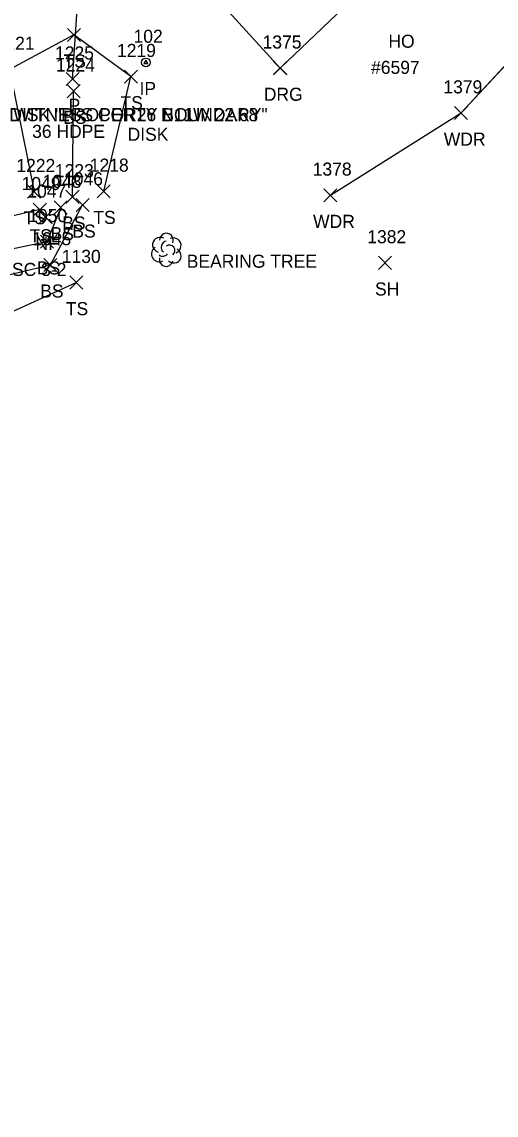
# Model space of a CAD drawing. Extents: x 1528286 to 1556263, y 492387 to 508952.
# Drawn here: x 1528944.2 to 1529016.8, y 492794 to 492961.3 of the extents above; entities that cross this region are included whole.
import ezdxf

# ---------------------------------------------------------------- set-up
doc = ezdxf.new("R2010")
doc.units = 0
for name, color, linetype in [('D_A', 7, 'Continuous'), ('D_C', 7, 'Continuous'), ('D_I', 7, 'Continuous'), ('D_TIC', 7, 'Continuous'), ('DCP', 7, 'Continuous'), ('L_A', 7, 'Continuous'), ('L_C', 7, 'Continuous'), ('L_I', 7, 'Continuous'), ('L_TIC', 7, 'Continuous'), ('LAWA', 7, 'Continuous'), ('LELB', 7, 'Continuous'), ('Level 14', 7, 'Continuous'), ('M_A', 7, 'Continuous'), ('M_C', 7, 'Continuous'), ('M_I', 7, 'Continuous'), ('MPIR', 7, 'Continuous'), ('R_A', 7, 'Continuous'), ('R_I', 7, 'Continuous'), ('R_TIC', 7, 'Continuous'), ('RDG', 7, 'Continuous')]:
    doc.layers.add(name, color=color, linetype=linetype)

msp = doc.modelspace()

# ---------------------------------------------------------------- linework, layer by layer
at = {"layer": 'D_TIC'}
for points in [[(1528950.98, 492951.57), (1528952.98, 492953.57)], [(1528952.98, 492951.57), (1528950.98, 492953.57)], [(1528950.98, 492951.57), (1528952.98, 492953.57)], [(1528952.98, 492951.57), (1528950.98, 492953.57)]]:
    msp.add_lwpolyline(points, dxfattribs=at)
at = {"layer": 'DCP'}
msp.add_lwpolyline([(1528951.98, 492952.57), (1528957.21, 493031.06)], dxfattribs=at)
msp.add_lwpolyline([(1528951.98, 492952.57), (1528957.21, 493031.06)], dxfattribs=at)
at = {"layer": 'L_TIC'}
for points in [[(1528951.19, 492958.33), (1528953.19, 492960.33)], [(1528953.19, 492958.33), (1528951.19, 492960.33)], [(1528951.19, 492958.33), (1528953.19, 492960.33)], [(1528953.19, 492958.33), (1528951.19, 492960.33)], [(1528959.9, 492951.95), (1528961.9, 492953.95)], [(1528961.9, 492951.95), (1528959.9, 492953.95)], [(1528959.9, 492951.95), (1528961.9, 492953.95)], [(1528961.9, 492951.95), (1528959.9, 492953.95)], [(1528951.13, 492949.72), (1528953.13, 492951.72)], [(1528953.13, 492949.72), (1528951.13, 492951.72)], [(1528951.13, 492949.72), (1528953.13, 492951.72)], [(1528953.13, 492949.72), (1528951.13, 492951.72)], [(1529010.39, 492946.38), (1529012.39, 492948.38)], [(1529012.39, 492946.38), (1529010.39, 492948.38)], [(1529010.39, 492946.38), (1529012.39, 492948.38)], [(1529012.39, 492946.38), (1529010.39, 492948.38)], [(1528945.08, 492934.35), (1528947.08, 492936.35)], [(1528947.08, 492934.35), (1528945.08, 492936.35)], [(1528945.08, 492934.35), (1528947.08, 492936.35)], [(1528947.08, 492934.35), (1528945.08, 492936.35)], [(1528950.96, 492933.55), (1528952.96, 492935.55)], [(1528952.96, 492933.55), (1528950.96, 492935.55)], [(1528950.96, 492933.55), (1528952.96, 492935.55)], [(1528952.96, 492933.55), (1528950.96, 492935.55)], [(1528955.74, 492934.4), (1528957.74, 492936.4)], [(1528957.74, 492934.4), (1528955.74, 492936.4)], [(1528955.74, 492934.4), (1528957.74, 492936.4)], [(1528957.74, 492934.4), (1528955.74, 492936.4)], [(1528990.4, 492933.8), (1528992.4, 492935.8)], [(1528992.4, 492933.8), (1528990.4, 492935.8)], [(1528990.4, 492933.79), (1528992.4, 492935.79)], [(1528992.4, 492933.79), (1528990.4, 492935.79)], [(1528949.17, 492931.92), (1528951.17, 492933.92)], [(1528951.17, 492931.92), (1528949.17, 492933.92)], [(1528949.17, 492931.92), (1528951.17, 492933.92)], [(1528951.17, 492931.92), (1528949.17, 492933.92)], [(1528952.5, 492932.31), (1528954.5, 492934.31)], [(1528954.5, 492932.31), (1528952.5, 492934.31)], [(1528952.5, 492932.31), (1528954.5, 492934.31)], [(1528954.5, 492932.31), (1528952.5, 492934.31)], [(1528945.97, 492931.59), (1528947.97, 492933.59)], [(1528947.97, 492931.59), (1528945.97, 492933.59)], [(1528945.97, 492931.59), (1528947.97, 492933.59)], [(1528947.97, 492931.59), (1528945.97, 492933.59)], [(1528946.83, 492930.44), (1528948.83, 492932.44)], [(1528948.83, 492930.44), (1528946.83, 492932.44)], [(1528946.83, 492930.44), (1528948.83, 492932.44)], [(1528948.83, 492930.44), (1528946.83, 492932.44)], [(1528947.06, 492926.68), (1528949.06, 492928.68)], [(1528949.06, 492926.68), (1528947.06, 492928.68)], [(1528947.06, 492926.68), (1528949.06, 492928.68)], [(1528949.06, 492926.68), (1528947.06, 492928.68)], [(1528998.75, 492923.45), (1529000.75, 492925.45)], [(1529000.75, 492923.45), (1528998.75, 492925.45)], [(1528998.75, 492923.45), (1529000.75, 492925.45)], [(1529000.75, 492923.45), (1528998.75, 492925.45)], [(1528947.59, 492923.14), (1528949.59, 492925.14)], [(1528949.59, 492923.14), (1528947.59, 492925.14)], [(1528947.59, 492923.14), (1528949.59, 492925.14)], [(1528949.59, 492923.14), (1528947.59, 492925.14)], [(1528951.54, 492920.44), (1528953.54, 492922.44)], [(1528953.54, 492920.44), (1528951.54, 492922.44)], [(1528951.54, 492920.44), (1528953.54, 492922.44)], [(1528953.54, 492920.44), (1528951.54, 492922.44)]]:
    msp.add_lwpolyline(points, dxfattribs=at)
at = {"layer": 'LAWA'}
for points in [[(1528991.4, 492934.8), (1529011.39, 492947.38), (1529021.11, 492957.87)], [(1528991.4, 492934.79), (1529011.39, 492947.38), (1529021.12, 492957.87)]]:
    msp.add_lwpolyline(points, dxfattribs=at)
at = {"layer": 'LELB'}
for points in [[(1528956.74, 492935.4), (1528960.9, 492952.95), (1528952.19, 492959.33), (1528942.34, 492954.05), (1528946.08, 492935.35)], [(1528956.74, 492935.4), (1528960.9, 492952.95), (1528952.19, 492959.33), (1528942.34, 492954.05), (1528946.08, 492935.35)], [(1528951.96, 492934.55), (1528952.13, 492950.72)], [(1528951.96, 492934.55), (1528952.13, 492950.72)], [(1528946.97, 492932.59), (1528919.96, 492926.16), (1528896.4, 492920.64), (1528892.93, 492919.08), (1528869.96, 492910.98), (1528843.06, 492896.38), (1528834.23, 492890.27), (1528806.99, 492871.86), (1528782.49, 492854.98), (1528750.99, 492833.05), (1528710.78, 492805.36), (1528694.19, 492792.45), (1528682.22, 492773.58), (1528672.78, 492775.79)], [(1528946.97, 492932.59), (1528919.96, 492926.16), (1528896.4, 492920.64), (1528892.93, 492919.08), (1528869.96, 492910.98), (1528843.06, 492896.38), (1528834.23, 492890.27), (1528806.99, 492871.86), (1528782.49, 492854.98), (1528750.99, 492833.05), (1528710.78, 492805.36), (1528694.19, 492792.45), (1528682.22, 492773.58), (1528672.78, 492775.79)], [(1528950.17, 492932.92), (1528948.06, 492927.68), (1528921.83, 492922.22), (1528901.57, 492912.91), (1528890.83, 492909.11), (1528874.51, 492905.43), (1528854.68, 492893.94), (1528843.94, 492888.14)], [(1528950.17, 492932.92), (1528948.06, 492927.68), (1528921.83, 492922.22), (1528901.57, 492912.91), (1528890.83, 492909.11), (1528874.51, 492905.43), (1528854.68, 492893.94), (1528843.94, 492888.14)], [(1528851.54, 492889.67), (1528882.3, 492901.37), (1528923.16, 492918.13), (1528948.59, 492924.14), (1528953.5, 492933.31)], [(1528851.54, 492889.67), (1528882.3, 492901.37), (1528923.16, 492918.13), (1528948.59, 492924.14), (1528953.5, 492933.31)], [(1528887.29, 492889.3), (1528894.85, 492900.08), (1528920.26, 492906.76), (1528952.54, 492921.44)], [(1528887.29, 492889.3), (1528894.85, 492900.08), (1528920.26, 492906.76), (1528952.54, 492921.44)]]:
    msp.add_lwpolyline(points, dxfattribs=at)
at = {"layer": 'Level 14'}
msp.add_line((1528966.29, 492926.49), (1528966.29, 492926.49), dxfattribs=at)
msp.add_line((1528966.29, 492926.49), (1528966.29, 492926.49), dxfattribs=at)
msp.add_arc((1528966.34, 492927.93), 1.05, 335.5272, 180.9563, dxfattribs=at)
for centre, major_axis, ratio, start_param, end_param in [((1528965.5, 492927.16), (1.21, -0.51), 0.895232, 1.570796, 4.712389), ((1528966.09, 492926.95), (-0.208, -0.792), 0.645439, 3.141593, 6.283185), ((1528966.79, 492926.33), (-0.5, 0.667), 0.989748, 3.141593, 6.283185), ((1528967.34, 492927.08), (-1.14, -0.48), 0.949671, 1.570796, 4.712389), ((1528965.21, 492925.78), (0.58, -1.04), 0.959034, 3.141593, 6.283185), ((1528965.84, 492925.74), (-0.625, -0.083), 0.423636, 0, 3.141593), ((1528967.29, 492925.66), (-1.09, 0.79), 0.841452, 1.570796, 4.712389), ((1528966.29, 492924.99), (0.26, 1.06), 0.942809, 1.570796, 4.712389)]:
    msp.add_ellipse(centre, major_axis=major_axis, ratio=ratio, start_param=start_param, end_param=end_param, dxfattribs=at)
at = {"layer": 'MPIR'}
msp.add_lwpolyline([(1528963.17, 492955.45), (1528962.88, 492954.95), (1528963.46, 492954.95)], close=True, dxfattribs=at)
msp.add_lwpolyline([(1528963.17, 492955.45), (1528962.88, 492954.95), (1528963.46, 492954.95)], close=True, dxfattribs=at)
msp.add_circle((1528963.17, 492955.12), 0.667, dxfattribs=at)
msp.add_circle((1528963.17, 492955.12), 0.667, dxfattribs=at)
at = {"layer": 'R_TIC'}
for points in [[(1528982.73, 492953.25), (1528984.73, 492955.25)], [(1528984.73, 492953.25), (1528982.73, 492955.25)], [(1528982.73, 492953.24), (1528984.73, 492955.24)], [(1528984.73, 492953.24), (1528982.73, 492955.24)]]:
    msp.add_lwpolyline(points, dxfattribs=at)
at = {"layer": 'RDG'}
for points in [[(1528996.65, 492966.62), (1528983.73, 492954.24), (1528967.43, 492972.19), (1528961.79, 492980.14)], [(1528996.65, 492966.63), (1528983.73, 492954.25), (1528967.42, 492972.19), (1528961.79, 492980.14)]]:
    msp.add_lwpolyline(points, dxfattribs=at)

# ---------------------------------------------------------------- texts
at = {"layer": 'D_A'}
msp.add_text('P', height=2, dxfattribs=at).set_placement((1528951.36, 492947.57))
msp.add_text('P', height=2, dxfattribs=at).set_placement((1528951.36, 492947.57))
at = {"layer": 'D_C'}
msp.add_text('36 HDPE', height=2, dxfattribs=at).set_placement((1528945.79, 492943.57))
msp.add_text('36 HDPE', height=2, dxfattribs=at).set_placement((1528945.79, 492943.57))
at = {"layer": 'D_I'}
msp.add_text('1225', height=2, dxfattribs=at).set_placement((1528949.29, 492955.57))
msp.add_text('1225', height=2, dxfattribs=at).set_placement((1528949.29, 492955.57))
at = {"layer": 'L_A'}
for s, p in [('HO', (1529000.28, 492957.36)), ('HO', (1529000.28, 492957.36)), ('TS', (1528950.6, 492954.33)), ('TS', (1528950.6, 492954.33)), ('TS', (1528959.31, 492947.95)), ('TS', (1528959.31, 492947.95)), ('BS', (1528950.57, 492945.72)), ('BS', (1528950.57, 492945.72)), ('WDR', (1529008.75, 492942.38)), ('WDR', (1529008.76, 492942.38)), ('TS', (1528944.48, 492930.35)), ('TS', (1528944.48, 492930.35)), ('TS', (1528955.15, 492930.4)), ('TS', (1528955.15, 492930.4)), ('BS', (1528950.4, 492929.55)), ('BS', (1528950.4, 492929.55)), ('WDR', (1528988.76, 492929.8)), ('WDR', (1528988.76, 492929.79)), ('TS', (1528945.38, 492927.59)), ('TS', (1528945.38, 492927.59)), ('BS', (1528948.61, 492927.92)), ('BS', (1528948.61, 492927.92)), ('BS', (1528951.94, 492928.31)), ('BS', (1528951.94, 492928.31)), ('NF', (1528946.31, 492926.44)), ('NF', (1528946.31, 492926.44)), ('BS', (1528946.5, 492922.68)), ('BS', (1528946.5, 492922.68)), ('BS', (1528947.03, 492919.14)), ('BS', (1528947.03, 492919.14)), ('SH', (1528998.23, 492919.45)), ('SH', (1528998.23, 492919.45)), ('TS', (1528950.95, 492916.44)), ('TS', (1528950.95, 492916.44))]:
    msp.add_text(s, height=2, dxfattribs=at).set_placement(p)
at = {"layer": 'L_C'}
for s, p in [('#6597', (1528997.63, 492953.36)), ('#6597', (1528997.63, 492953.36)), ('SC 3-2', (1528942.71, 492922.44)), ('SC 3-2', (1528942.71, 492922.44))]:
    msp.add_text(s, height=2, dxfattribs=at).set_placement(p)
at = {"layer": 'L_I'}
for s, p in [('1221', (1528940.22, 492957.05)), ('1221', (1528940.22, 492957.05)), ('1219', (1528958.77, 492955.95)), ('1219', (1528958.77, 492955.95)), ('1224', (1528949.43, 492953.72)), ('1224', (1528949.43, 492953.72)), ('1379', (1529008.69, 492950.38)), ('1379', (1529008.69, 492950.38)), ('1218', (1528954.61, 492938.4)), ('1218', (1528954.61, 492938.4)), ('1222', (1528943.38, 492938.35)), ('1222', (1528943.38, 492938.35)), ('1223', (1528949.27, 492937.55)), ('1223', (1528949.27, 492937.55)), ('1378', (1528988.7, 492937.8)), ('1378', (1528988.71, 492937.79)), ('1049', (1528944.19, 492935.59)), ('1049', (1528944.19, 492935.59)), ('1048', (1528947.39, 492935.92)), ('1048', (1528947.39, 492935.92)), ('1046', (1528950.67, 492936.31)), ('1046', (1528950.67, 492936.31)), ('1047', (1528945.06, 492934.44)), ('1047', (1528945.06, 492934.44)), ('1050', (1528945.2, 492930.68)), ('1050', (1528945.2, 492930.68)), ('1045', (1528945.82, 492927.14)), ('1045', (1528945.82, 492927.14)), ('1382', (1528997.05, 492927.45)), ('1382', (1528997.05, 492927.45)), ('1130', (1528950.33, 492924.44)), ('1130', (1528950.33, 492924.44))]:
    msp.add_text(s, height=2, dxfattribs=at).set_placement(p)
at = {"layer": 'M_A'}
msp.add_text('IP', height=2, dxfattribs=at).set_placement((1528962.22, 492950.12))
msp.add_text('IP', height=2, dxfattribs=at).set_placement((1528962.22, 492950.12))
at = {"layer": 'M_C'}
for s, p in [('DISK "PROPERTY BOUNDARY"', (1528942.31, 492946.12)), ('WITNESS COR26 N11W 22.68', (1528942.92, 492946.12)), ('DISK', (1528960.39, 492943.12)), ('BEARING TREE', (1528969.44, 492923.7))]:
    msp.add_text(s, height=2, dxfattribs=at).set_placement(p)
at = {"layer": 'M_I'}
msp.add_text('102', height=2, dxfattribs=at).set_placement((1528961.3, 492958.12))
msp.add_text('102', height=2, dxfattribs=at).set_placement((1528961.3, 492958.12))
at = {"layer": 'R_A'}
for p in [(1528981.22, 492949.24), (1528981.22, 492949.25)]:
    msp.add_text('DRG', height=2, dxfattribs=at).set_placement(p)
at = {"layer": 'R_I'}
for p in [(1528981.04, 492957.24), (1528981.03, 492957.25)]:
    msp.add_text('1375', height=2, dxfattribs=at).set_placement(p)

doc.saveas('drawing.dxf')
